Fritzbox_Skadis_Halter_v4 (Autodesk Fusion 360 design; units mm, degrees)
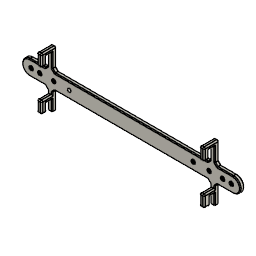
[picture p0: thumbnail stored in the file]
description: Part Number
part number: Fritzbox 7430 Halter
base_feature "Base Feature"
sketch "Skizze" plane through (0, 0, 0) normal (0, -1, 0) x axis (1, 0, 0)
  line L1 (171.5, 23.0729) -> (171.5, 9.6893)
  line L2 (168.5, 9.6893) -> (168.5, 23.0729)
  line L3 (165.5607, 6.75) -> (168.5, 9.6893)
  line L4 (14.4393, 6.75) -> (165.5607, 6.75)
  line L5 (11.5, 9.6893) -> (14.4393, 6.75)
  line L6 (11.5, 23.0729) -> (11.5, 9.6893)
  line L7 (8.5, 9.6893) -> (8.5, 23.0729)
  line L8 (5.5607, 6.75) -> (8.5, 9.6893)
  line L9 (0, 6.75) -> (5.5607, 6.75)
  line L10 (5.5607, -6.75) -> (0, -6.75)
  line L11 (8.5, -9.6893) -> (5.5607, -6.75)
  line L12 (8.5, -12.6044) -> (8.5, -9.6893)
  line L13 (11, -12.5) -> (9, -12.5)
  line L14 (11.5, -9.6893) -> (11.5, -12.6044)
  line L15 (14.4393, -6.75) -> (11.5, -9.6893)
  line L16 (165.5607, -6.75) -> (14.4393, -6.75)
  line L17 (168.5, -9.6893) -> (165.5607, -6.75)
  line L18 (168.5, -12.6044) -> (168.5, -9.6893)
  line L19 (171, -12.5) -> (169, -12.5)
  line L20 (171.5, -9.6893) -> (171.5, -12.6044)
  line L21 (174.4393, -6.75) -> (171.5, -9.6893)
  line L22 (180, -6.75) -> (174.4393, -6.75)
  line L23 (174.4393, 6.75) -> (180, 6.75)
  line L24 (171.5, 9.6893) -> (174.4393, 6.75)
  curve K1 (181.0813, 1.2715) -> (178.0148, 0.5302)
  curve K2 (181.099, 1.2521) -> (181.0793, 1.2691)
  curve K3 (178.0113, -0.5318) -> (181.0794, -1.2691)
  curve K4 (1.0813, 1.2714) -> (-1.9852, 0.5302)
  curve K5 (-1.9886, -0.5317) -> (1.0794, -1.2691)
  line L25 (180, 0) -> (0, 0)
  line L26 (90, 0) -> (180, 0)
  line L27 (166.5, 0) -> (90, 0)
  line L28 (13.5, 0) -> (90, 0)
  line L29 (-8.5, 0) -> (90, 0)
  line L30 (188.5, 0) -> (90, 0)
  line L31 (151, 0) -> (90, 0)
  line L32 (29, 0) -> (90, 0)
  line L33 (40, 0) -> (90, 0)
  line L34 (140, 0) -> (90, 0)
  arc A1 centre (170, 24.75) radius 2.25 clockwise from (171.5, 23.0729) to (168.5, 23.0729)
  arc A2 centre (10, 24.75) radius 2.25 clockwise from (11.5, 23.0729) to (8.5, 23.0729)
  arc A3 centre (0, 0) radius 6.75 clockwise from (0, -6.75) to (0, 6.75)
  arc A4 centre (9, -13.75) radius 1.25 clockwise from (8.5, -12.6044) to (9, -12.5)
  arc A5 centre (11, -13.75) radius 1.25 clockwise from (11, -12.5) to (11.5, -12.6044)
  arc A6 centre (169, -13.75) radius 1.25 clockwise from (168.5, -12.6044) to (169, -12.5)
  arc A7 centre (171, -13.75) radius 1.25 clockwise from (171, -12.5) to (171.5, -12.6044)
  arc A8 centre (180, 0) radius 6.75 clockwise from (180, 6.75) to (180, -6.75)
  arc A9 centre (180, 0) radius 1.666 clockwise from (181.099, 1.2521) to (181.0794, -1.2691)
  arc A10 centre (180, 0) radius 2.0548 clockwise from (178.0149, -0.5306) to (178.0148, 0.5302)
  arc A11 centre (0, 0) radius 1.666 clockwise from (1.0793, 1.2691) to (1.0794, -1.2691)
  arc A12 centre (0, 0) radius 2.0547 clockwise from (-1.9851, -0.5305) to (-1.9852, 0.5302)
  point P1 (0, 0)
  point P55 (0, 0)
  point P40 (180, 0)
  point P56 (180, 0)
  point P57 (90, 0)
  point P58 (166.5, 0)
  point P59 (13.5, 0)
  point P60 (-8.5, 0)
  point P61 (188.5, 0)
  point P62 (151, 0)
  point P63 (29, 0)
  point P64 (40, 0)
  point P65 (140, 0)
  coincident P1 P55
  coincident P40 P56
  parallel L25 L26
  parallel L26 L27
  parallel L25 L28
  horizontal L29
  parallel L27 L30
  parallel L27 L31
  parallel L29 L32
  parallel L29 L33
  parallel L31 L34
  dimension "d1" distance P56 P57 = 90
  dimension "d2" distance P57 P58 = 76.5
  dimension "d3" distance P57 P59 = 76.5
  dimension "d19" distance P57 P60 = 98.5
  dimension "d20" distance P57 P61 = 98.5
  dimension "d31" distance P57 P62 = 61 (= "( 122 / 2 ) * 1 mm")
  dimension "d32" distance P57 P63 = 61
  dimension "d43" distance P57 P64 = 50
  dimension "d44" distance P57 P65 = 50
hole "Bohrung1" HoleDepth 1.2 HoleDiameter 0.318 TipAngle 118
hole "Bohrung2" HoleDepth 13 HoleDiameter 3.332 TipAngle 118
move_face "Fläche verschieben1"
hole "Bohrung3" HoleDepth 4.5 HoleDiameter 3.332 TipAngle 118
move_face "Fläche verschieben2"
move_face "Fläche verschieben3"
hole "Bohrung4" HoleDepth 6 HoleDiameter 3.332 TipAngle 118
hole "Bohrung5" HoleDepth 4 HoleDiameter 3.332 TipAngle 118
hole "Bohrung6" HoleDepth 8 HoleDiameter 3.332 TipAngle 118
hole "Bohrung7" HoleDepth 9 HoleDiameter 3.332 TipAngle 118
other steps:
thread "Gewinde1" ThreadOffset 0 ThreadDepth 7.4
thread "Gewinde2" ThreadOffset 0 ThreadDepth 7.4
thread "Gewinde3" ThreadOffset 0 ThreadDepth 7.4
thread "Gewinde4" ThreadOffset 0 ThreadDepth 7.4
thread "Gewinde5" ThreadOffset 0 ThreadDepth 7.4
thread "Gewinde6" ThreadOffset 0 ThreadDepth 7.4
thread "Gewinde7" ThreadOffset 0 ThreadDepth 7.4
